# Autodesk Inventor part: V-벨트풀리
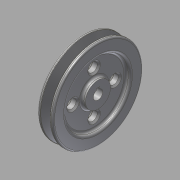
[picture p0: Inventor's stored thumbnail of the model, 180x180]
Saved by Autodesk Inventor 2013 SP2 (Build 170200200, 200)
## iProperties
Created: 2015-09
Part Number: V-벨트풀리
Material: 강철, 연강
Document SubType Name: Modeling
Designer: mduedu
Density: 1 g/cm^3
Author: mduedu
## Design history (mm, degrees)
sketch "스케치1"
  geometry: L1 (-10, 0)-(10, 0); L2 (-10, 0)-(-10, 57.5); L3 (-10, 57.5)-(-6.062, 57.5); L4 (-6.062, 57.5)-(-2.001, 45); L5 (-2.001, 45)-(2.001, 45); L6 (2.001, 45)-(6.062, 57.5); L7 (6.062, 57.5)-(10, 57.5); L8 (10, 57.5)-(10, 0); L9 (0, 0)-(0, 45); L10 (-10, 53)-(10, 53); 3 further points
  constraints: 20 end point, 6 point on line, 3 perpendicular, 2 midpoint, 2 parallel, 2 symmetric about line, 1 coincident, 1 collinear, 1 equal length, 1 horizontal, 1 vertical, 1 vertical alignment
  dimensions: "d0" = 20 distance between parallel lines of L8 L2; "d2" = 115 diameter of L3 L1; "d5" = 8 distance between parallel lines of L5 L10; "d6" = 9.2 distance of point (4.6, 53) point (-4.6, 53); "d7" = 36 deg angle of L6 L4; "d40" = 4.5 distance between parallel lines of L10 L3
revolve "회전1" sketch "스케치1" stored, may be unused: angle "d8" = 90 deg
sketch "스케치2"
  geometry: C1 r 16 at (0, 0); C2 r 41 at (0, 0); 1 further point
  constraints: 2 centre point, 2 coincident
  dimensions: "d9" = 32 diameter of C1; "d41" = 82 diameter of C2
extrude "돌출5" cut sketch "스케치2" distance "d42" = 5; taper "d43" = 0 deg
hole "구멍2" diameter "d46" = 12; stored, may be unused: countersink angle "d50" = 90 deg, drill point angle "d52" = 118 deg; dims "d44" = 10, "d45" = 10, "d47" = 6, "d48" = 4, "d49" = 2, "d51" = 8
sketch "스케치8"
  geometry: L1 (-2, 5.657)-(2, 5.657); L2 (2, 5.657)-(2, 7.8); L3 (2, 7.8)-(-2, 7.8); L4 (-2, 7.8)-(-2, 5.657); A1 r 6 centre (0, 0) between (-2, 5.657) and (2, 5.657) reference; 1 further point
  constraints: 8 end point, 2 parallel, 2 point on circle, 1 horizontal, 1 perpendicular
  dimensions: "d53" = 4 distance of L2.end L3.end; "d55" = 13.8 dimension on A1 L3
extrude "돌출6" cut sketch "스케치8" stored distance "d56" = 5; taper "d57" = 0 deg
sketch "스케치9"
  geometry: C1 r 6 at (0, 27); 1 further point
  constraints: 1 centre point, 1 vertical alignment
  dimensions: "d61" = 12 diameter of C1; "d62" = 27 distance of C1.centre point (0, 0)
extrude "돌출7" cut sketch "스케치9" stored distance "d63" = 5; taper "d64" = 0 deg
chamfer "모따기3" distance "d65" = 2; stored, may be unused: second distance "d66" = 2, angle "d67" = 45 deg
fillet "모깎기5" dims "d71" = 2, "d72" = 1, "d73" = 0.5
fillet "모깎기6" dims "d74" = 3
fillet "모깎기7" dims "d75" = 3
fillet "모깎기8" dims "d76" = 3
sketch "스케치10"
  geometry: C1 r 47.5 at (0, 0); 1 further point
  constraints: 1 centre point, 1 coincident, 1 other
  dimensions: "d77" = 95 diameter of C1
extrude "돌출8" join sketch "스케치10" distance "d80" = 0.5; taper "d81" = 0 deg
node "솔리드1"
mirror "대칭2"
pattern_circular "원형 패턴1" dims "d69" = 360 deg
